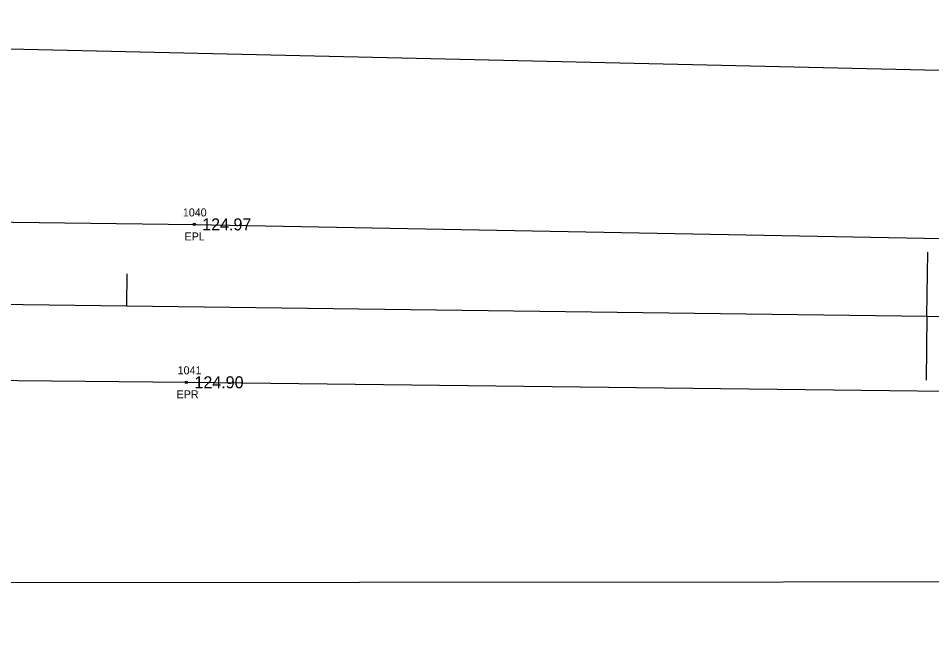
# Model space of a CAD drawing. Extents: x 2374510 to 2377726, y 1024129 to 1025429.
# Drawn here: x 2376293 to 2376407.1, y 1024889.6 to 1024965.9 of the extents above; entities that cross this region are included whole.
import ezdxf

# ---------------------------------------------------------------- set-up
doc = ezdxf.new("R2010")
doc.units = 0
for name, color, linetype in [('RD_EX_Road', 7, 'Continuous'), ('RD_EX_Road_txCode', 7, 'Continuous'), ('RD_EX_TX_Road_ELEV', 7, 'Continuous'), ('RD_EX_VEG', 7, 'Continuous'), ('RD_HC_Cl', 7, 'Continuous'), ('RD_HC_Data_Tic', 7, 'Continuous'), ('RD_SMD_Locator', 7, 'Continuous')]:
    doc.layers.add(name, color=color, linetype=linetype)

msp = doc.modelspace()

# ---------------------------------------------------------------- linework, layer by layer
at = {"layer": 'RD_EX_Road'}
for points in [[(2375814.75, 1024926.04), (2375866.75, 1024934.16), (2375917.59, 1024939.49), (2375973.63, 1024942.9), (2376030.48, 1024943.85), (2376125.42, 1024942.84), (2376221.25, 1024941.27), (2376314.97, 1024940.08), (2376410.64, 1024938.26), (2376471.87, 1024938.44)], [(2375818.02, 1024906.46), (2375868.67, 1024914.36), (2375919.37, 1024919.49), (2375974.01, 1024923.01), (2376030.21, 1024923.67), (2376124.55, 1024922.83), (2376221.09, 1024921.25), (2376314, 1024920.33), (2376408.92, 1024919.22), (2376471.42, 1024917.38)]]:
    msp.add_lwpolyline(points, dxfattribs=at)
at = {"layer": 'RD_EX_VEG'}
for points in [[(2375821.28, 1024948.02), (2375920.08, 1024958.54), (2375972.69, 1024962.41), (2376124.69, 1024965.87), (2376562.5, 1024955.85), (2376666.61, 1024955.06), (2377217.56, 1024949.87)], [(2375819.71, 1024889.63), (2375920.06, 1024900.35), (2376123.72, 1024895.17), (2376547.52, 1024895.5), (2377115.53, 1024890.13), (2377218, 1024892.46)]]:
    msp.add_lwpolyline(points, dxfattribs=at)
at = {"layer": 'RD_HC_Cl'}
msp.add_line((2376010.95, 1024933.69), (2377093.47, 1024919.75), dxfattribs=at)
at = {"layer": 'RD_HC_Data_Tic'}
for p, q in [((2376406.55, 1024928.6), (2376406.65, 1024936.59)), ((2376306.56, 1024929.88), (2376306.61, 1024933.88)), ((2376406.55, 1024928.6), (2376406.45, 1024920.6))]:
    msp.add_line(p, q, dxfattribs=at)
at = {"layer": 'RD_SMD_Locator'}
for centre in [(2376314.97, 1024940.08), (2376314, 1024920.33)]:
    msp.add_circle(centre, 0.15, dxfattribs=at)

# ---------------------------------------------------------------- texts
at = {"layer": 'RD_EX_Road_txCode'}
for s, p in [('1040', (2376313.55, 1024941.08)), ('EPL', (2376313.77, 1024938.08)), ('1041', (2376312.9, 1024921.33)), ('EPR', (2376312.77, 1024918.33))]:
    msp.add_text(s, height=1, dxfattribs=at).set_placement(p)
at = {"layer": 'RD_EX_TX_Road_ELEV'}
for s, p in [('124.97', (2376315.97, 1024939.33)), ('124.90', (2376315, 1024919.58))]:
    msp.add_text(s, height=1.5, dxfattribs=at).set_placement(p)

doc.saveas('drawing.dxf')
